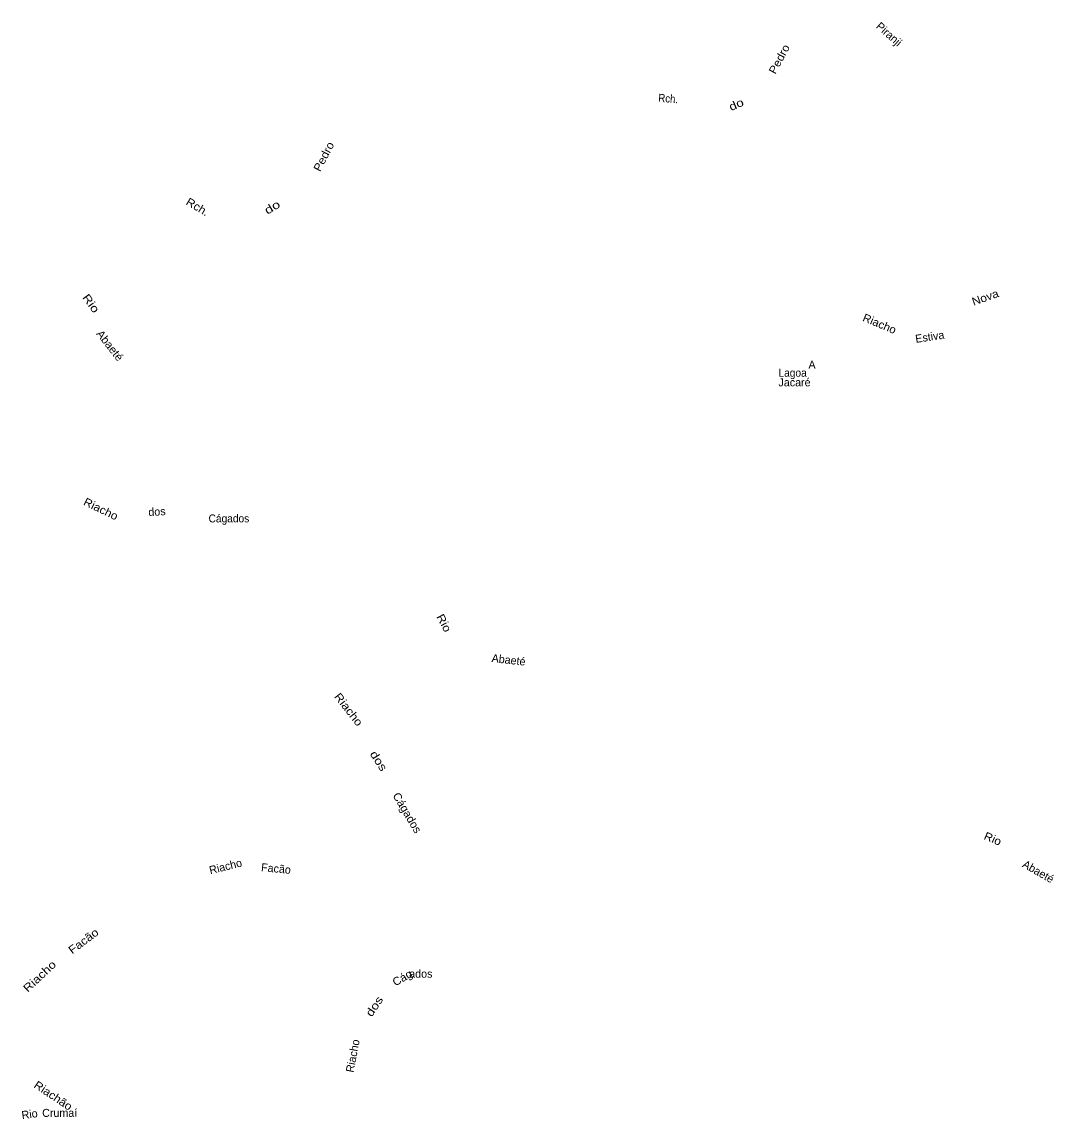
# Model space of a CAD drawing. Extents: x 649844 to 663669, y 8700676 to 8714511.
# Drawn here: x 649844 to 656294, y 8700833 to 8707685 of the extents above; entities that cross this region are included whole.
import ezdxf
from ezdxf.enums import TextEntityAlignment as Align

# ---------------------------------------------------------------- set-up
doc = ezdxf.new("R2010")
doc.units = 0
doc.header["$LTSCALE"] = 20
doc.layers.add('20', color=7, linetype='Continuous')
doc.layers.add('51', color=7, linetype='Continuous')

msp = doc.modelspace()

# ---------------------------------------------------------------- texts
at = {"layer": '20'}
msp.add_text('A', height=50, rotation=0.001, dxfattribs=at).set_placement((654759.17, 8705519.29))
at = {"layer": '51'}
for s, rotation, p in [('Piranji', 318.589, (655246.38, 8707589.4)), ('Estiva', 8.564, (655520.59, 8705693.65)), ('dos', 3.758, (650689.47, 8704601.57)), ('Abaeté', 353.729, (652882.71, 8703675.97)), ('Riacho', 13.986, (651122.51, 8702386.58)), ('Facão', 354.564, (651429.57, 8702372.65)), ('Abaeté', 330.172, (656183.01, 8702357.15)), ('ados', 359.969, (652336.56, 8701715.63)), ('Riacho', 79.205, (651935.7, 8701223.2)), ('Rio', 7.693, (649895.14, 8700838.96)), ('Crumaí', 0.14, (650080.31, 8700846.63))]:
    msp.add_text(s, height=50, rotation=rotation, dxfattribs=at).set_placement(p, align=Align.CENTER)
for s, rotation, width, p in [('Pedro', 61.91, 1.1, (654598.45, 8707441.05)), ('Rch.', 355.557, 0.9, (653880.83, 8707181.69)), ('do', 23.962, 1.25, (654317.94, 8707146.46)), ('Pedro', 62.571, 1.1, (651752.47, 8706832.65)), ('Rch.', 328.986, 1.1, (650928.89, 8706508.5)), ('do', 31.017, 1.35, (651420.97, 8706506.14)), ('Rio', 305.926, 1.25, (650255.63, 8705912.49)), ('Nova', 19.388, 1.1, (655871.82, 8705940.79)), ('Riacho', 337.199, 1.05, (655193.59, 8705776.94)), ('Abaeté', 308.161, 1.05, (650374.54, 8705648.44)), ('Riacho', 334.086, 1.1, (650326.72, 8704620.7)), ('Cágados', 0.05, 0.95, (651137.68, 8704559.22)), ('Rio', 297.848, 1.15, (652459.65, 8703919.44)), ('Riacho', 307.853, 1.15, (651865.83, 8703375.94)), ('dos', 302.94, 1.25, (652052.23, 8703056.53)), ('Cágados', 300.655, 1.05, (652229.99, 8702733.08)), ('Rio', 336.883, 1.1, (655901.2, 8702560.72)), ('Facão', 36.85, 1.15, (650243.4, 8701924.82)), ('Riacho', 43.123, 1.2, (649971.47, 8701706.61)), ('Cág', 29.993, 1.05, (652233.41, 8701693.25)), ('dos', 56.485, 1.25, (652067.06, 8701523.23)), ('Riachão', 326.166, 1.1, (650025.85, 8700958.57))]:
    msp.add_text(s, height=50, rotation=rotation, dxfattribs=dict(at, width=width)).set_placement(p, align=Align.CENTER)
at = {"layer": '51', "width": 0.95}
msp.add_text('Lagoa', height=50, dxfattribs=at).set_placement((654571.57, 8705469.02))
at = {"layer": '51'}
msp.add_text('Jacaré', height=50, dxfattribs=at).set_placement((654571.57, 8705409.02))

doc.saveas('drawing.dxf')
